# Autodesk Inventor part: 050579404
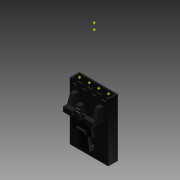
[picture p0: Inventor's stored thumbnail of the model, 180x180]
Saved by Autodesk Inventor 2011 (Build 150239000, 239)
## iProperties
Company: Autodesk Inc.
Created: 2006-09
Part Number: 050579404
Document SubType Name: Modeling
Designer: Autodesk Inc.
Density: 1 g/cm^3
Categories: <MemberInstance><Categories><Category DisplayName="" Mnemonic="CABLEANDHARNESS" InternalName="e4a7e005-5e42-4d16-b293-125e7f0d0512"><Category DisplayName="" Mne
Mass: 0.263499 g
Surface Area: 8.95077 cm^2
Volume: 0.263499 cm^3
GlobalPropertyList: <PropertyList/>
Author: Autodesk Inc.
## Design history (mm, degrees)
feature "Base1"
sketch "Sketch1"
  geometry: L1 (0.616, -2.515)-(0.616, -2.134) reference; L2 (0.381, -2.134)-(0.616, -2.134) reference; L3 (0.381, -0.381)-(0.381, -2.134) reference; L4 (9.754, -0.381)-(0.381, -0.381) reference; L5 (9.754, -2.134)-(9.754, -0.381) reference; L6 (9.506, -2.134)-(9.754, -2.134) reference; L7 (9.506, -2.515)-(9.506, -2.134) reference; L8 (10.135, -2.515)-(9.506, -2.515) reference; L9 (10.135, 0)-(10.135, -2.515) reference; L10 (0, 0)-(10.135, 0) reference; L11 (0, -2.515)-(0, 0) reference; L12 (0.616, -2.515)-(0, -2.515) reference; L13 (7.988, 0)-(10.135, 0) reference; L14 (10.135, 0)-(10.135, -2.515) reference; L15 (10.135, -2.515)-(0, -2.515) reference; L16 (0, -2.515)-(0, 0) reference; L17 (0, 0)-(2.146, 0) reference; L18 (2.146, 1.016)-(2.146, 0) reference; L19 (2.908, 1.016)-(2.146, 1.016) reference; L20 (2.908, 0)-(2.908, 1.016) reference; L21 (2.908, 0)-(7.226, 0) reference; L22 (7.226, 1.016)-(7.226, 0) reference; L23 (7.988, 1.016)-(7.226, 1.016) reference; L24 (7.988, 0)-(7.988, 1.016) reference; L25 (0.368, -2.146)-(0.368, -0.368) reference; L26 (2.146, -2.146)-(0.368, -2.146) reference; L27 (2.146, -0.368)-(2.146, -2.146) reference; L28 (0.368, -0.368)-(2.146, -0.368) reference; L29 (2.908, -2.146)-(2.908, -0.368) reference; L30 (4.686, -2.146)-(2.908, -2.146) reference; L31 (4.686, -0.368)-(4.686, -2.146) reference; L32 (2.908, -0.368)-(4.686, -0.368) reference; L33 (5.448, -2.146)-(5.448, -0.368) reference; L34 (7.226, -2.146)-(5.448, -2.146) reference; L35 (7.226, -0.368)-(7.226, -2.146) reference; L36 (5.448, -0.368)-(7.226, -0.368) reference; L37 (7.988, -2.146)-(7.988, -0.368) reference; L38 (9.766, -2.146)-(7.988, -2.146) reference; L39 (9.766, -0.368)-(9.766, -2.146) reference; L40 (7.988, -0.368)-(9.766, -0.368) reference; 12 further points
  constraints: 8 midpoint, 4 horizontal alignment, 4 vertical alignment
  node "Projected Loop1"
node "1"
node "2"
node "3"
node "4"
workplane "Work Plane1"
sketch "Sketch2"
  geometry: L1 (1.257, -1.257)-(8.877, -1.257); 1 further point
  constraints: 2 end point, 1 horizontal, 1 midpoint
workpoint "Work Point5"
workplane "Work Plane2"
sketch "Sketch3"
  geometry: 1 further point
workpoint "Work Point6"
body "Solid1"
other parameters: "d0" = 12.7, "d1" = 14.2875
